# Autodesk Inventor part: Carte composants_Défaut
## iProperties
Shininess: 64.0
Length Units: 11269
Angle Units: 11279
Time Units: 11290
Mass Units: 11283
Length Display Precision: 3
Angle Display Precision: 2
Compacted: True
Part Number: Carte composants_Défaut
Document SubType Name: Modeling
Created: 2006-01
Material: Par défaut
Designer: riri
Density: 0.0
Volumn: 0.0
Area: 0.0
PropertySet Name: Model Information
Control State: 0
Master: False
Checked Out: False
Author: riri
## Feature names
1. Base1
